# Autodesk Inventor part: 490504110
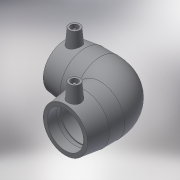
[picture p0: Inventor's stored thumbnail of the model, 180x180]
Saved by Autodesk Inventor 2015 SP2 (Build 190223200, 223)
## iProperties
Created: 2017-06
Part Number: 490504110
Material: Generic
Description: PLASSON 90° ELBOW 110
Document SubType Name: Modeling
Designer: KIM
Mass: 55.0731 g
Surface Area: 148.067 cm^2
Volume: 55.0731 cm^3
Density: 1 g/cm^3
Appearance: Default
Author: KIM
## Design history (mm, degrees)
derived "490504.ipt"
feature "Solid1::490504.ipt"
tag "TaggingFeature1"
body "Solid1"
other parameters: "d2" = 143, "d4" = 60.75, "d5" = 128.7, "d8" = 168 deg, "d10" = 31.6, "d11" = 10.53333, "d14" = 17.6296, "d19" = 3.52592, "d20" = 168 deg, "d22" = 131.56, "d23" = 143, "d24" = 127.6132, "d29" = 79, "d30" = 15, "d31" = 85.05, "d34" = 5 deg, "d35" = 15, "d39" = 5 deg, "d41" = 4, "d42" = 14, "d43" = 0, "d45" = 4, "d46" = 14, "d47" = 0, "d50" = 93.5, "d51" = 31.6, "d52" = 79, "d54" = 90 deg, "d67" = 45 deg, "d71" = 90 deg, "d75" = 7.15, "d82" = 45 deg, "d83" = 79, "d84" = 128.7, "d86" = 64.35, "d87" = 90 deg, "d90" = 79, "d91" = 0, "d92" = 79, "d93" = 0, "d94" = 90 deg, "d95" = 65.78, "d98" = 243, "d101" = 3, "d102" = 0, "d103" = 3, "d104" = 0, "d105" = 22.91, "d106" = 5.7275, "d107" = 243, "d110" = 43.45, "L_" = 243, "L_1" = 79, "D_" = 143, "A_" = 79, "d_2" = 12
